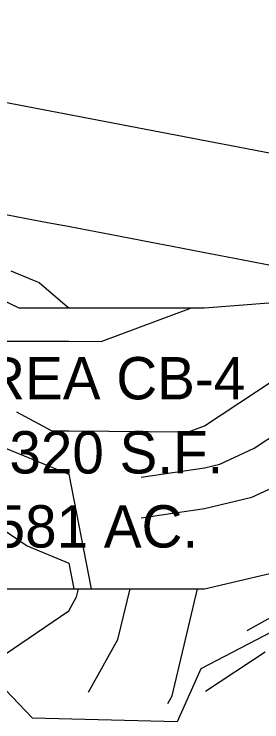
# Model space of a CAD drawing. Extents: x 2238 to 5457, y 2895 to 3316.
# Drawn here: x 3027 to 3085.6, y 3033.6 to 3200.8 of the extents above; entities that cross this region are included whole.
import ezdxf

# ---------------------------------------------------------------- set-up
doc = ezdxf.new("R2010")
doc.units = 0
for name, color, linetype in [('Default', 7, 'Continuous'), ('DESIGN - SCRATCH - User 2', 7, 'Continuous'), ('SURVEY - CENTERLINE - Preliminary', 7, 'Continuous'), ('SURVEY - DRAINAGE - Area Shapes', 7, 'Continuous')]:
    doc.layers.add(name, color=color, linetype=linetype)

msp = doc.modelspace()

# ---------------------------------------------------------------- linework, layer by layer
at = {"layer": 'DESIGN - SCRATCH - User 2'}
for points in [[(3025.06, 3153.5), (3029.97, 3152.56), (3034.88, 3151.62), (3039.79, 3150.68), (3044.7, 3149.74), (3049.61, 3148.8), (3054.53, 3147.86), (3059.44, 3146.92), (3064.35, 3145.98), (3069.26, 3145.04), (3074.17, 3144.1), (3079.08, 3143.16), (3083.99, 3142.22), (3088.9, 3141.28)], [(3025.06, 3153.5), (3029.97, 3152.56), (3034.88, 3151.62), (3039.79, 3150.68), (3044.7, 3149.74), (3049.61, 3148.8), (3054.53, 3147.86), (3059.44, 3146.92), (3064.35, 3145.98), (3069.26, 3145.04), (3074.17, 3144.1), (3079.08, 3143.16), (3083.99, 3142.22), (3088.9, 3141.28)], [(3025.06, 3153.5), (3029.97, 3152.56), (3034.88, 3151.62), (3039.79, 3150.68), (3044.7, 3149.74), (3049.61, 3148.8), (3054.53, 3147.86), (3059.44, 3146.92), (3064.35, 3145.98), (3069.26, 3145.04), (3074.17, 3144.1), (3079.08, 3143.16), (3083.99, 3142.22), (3088.9, 3141.28)], [(3025.06, 3153.5), (3029.97, 3152.56), (3034.88, 3151.62), (3039.79, 3150.68), (3044.7, 3149.74), (3049.61, 3148.8), (3054.53, 3147.86), (3059.44, 3146.92), (3064.35, 3145.98), (3069.26, 3145.04), (3074.17, 3144.1), (3079.08, 3143.16), (3083.99, 3142.22), (3088.9, 3141.28)], [(3025.06, 3153.5), (3029.97, 3152.56), (3034.88, 3151.62), (3039.79, 3150.68), (3044.7, 3149.74), (3049.61, 3148.8), (3054.53, 3147.86), (3059.44, 3146.92), (3064.35, 3145.98), (3069.26, 3145.04), (3074.17, 3144.1), (3079.08, 3143.16), (3083.99, 3142.22), (3088.9, 3141.28)], [(3025.06, 3153.5), (3029.97, 3152.56), (3034.88, 3151.62), (3039.79, 3150.68), (3044.7, 3149.74), (3049.61, 3148.8), (3054.53, 3147.86), (3059.44, 3146.92), (3064.35, 3145.98), (3069.26, 3145.04), (3074.17, 3144.1), (3079.08, 3143.16), (3083.99, 3142.22), (3088.9, 3141.28)], [(3025.06, 3153.5), (3029.97, 3152.56), (3034.88, 3151.62), (3039.79, 3150.68), (3044.7, 3149.74), (3049.61, 3148.8), (3054.53, 3147.86), (3059.44, 3146.92), (3064.35, 3145.98), (3069.26, 3145.04), (3074.17, 3144.1), (3079.08, 3143.16), (3083.99, 3142.22), (3088.9, 3141.28)], [(3025.06, 3153.5), (3029.97, 3152.56), (3034.88, 3151.62), (3039.79, 3150.68), (3044.7, 3149.74), (3049.61, 3148.8), (3054.53, 3147.86), (3059.44, 3146.92), (3064.35, 3145.98), (3069.26, 3145.04), (3074.17, 3144.1), (3079.08, 3143.16), (3083.99, 3142.22), (3088.9, 3141.28)], [(3025.06, 3153.5), (3029.97, 3152.56), (3034.88, 3151.62), (3039.79, 3150.68), (3044.7, 3149.74), (3049.61, 3148.8), (3054.53, 3147.86), (3059.44, 3146.92), (3064.35, 3145.98), (3069.26, 3145.04), (3074.17, 3144.1), (3079.08, 3143.16), (3083.99, 3142.22), (3088.9, 3141.28)], [(3025.06, 3153.5), (3029.97, 3152.56), (3034.88, 3151.62), (3039.79, 3150.68), (3044.7, 3149.74), (3049.61, 3148.8), (3054.53, 3147.86), (3059.44, 3146.92), (3064.35, 3145.98), (3069.26, 3145.04), (3074.17, 3144.1), (3079.08, 3143.16), (3083.99, 3142.22), (3088.9, 3141.28)], [(3025.06, 3153.5), (3029.97, 3152.56), (3034.88, 3151.62), (3039.79, 3150.68), (3044.7, 3149.74), (3049.61, 3148.8), (3054.53, 3147.86), (3059.44, 3146.92), (3064.35, 3145.98), (3069.26, 3145.04), (3074.17, 3144.1), (3079.08, 3143.16), (3083.99, 3142.22), (3088.9, 3141.28)], [(3025.06, 3153.5), (3029.97, 3152.56), (3034.88, 3151.62), (3039.79, 3150.68), (3044.7, 3149.74), (3049.61, 3148.8), (3054.53, 3147.86), (3059.44, 3146.92), (3064.35, 3145.98), (3069.26, 3145.04), (3074.17, 3144.1), (3079.08, 3143.16), (3083.99, 3142.22), (3088.9, 3141.28)], [(3025.06, 3153.5), (3029.97, 3152.56), (3034.88, 3151.62), (3039.79, 3150.68), (3044.7, 3149.74), (3049.61, 3148.8), (3054.53, 3147.86), (3059.44, 3146.92), (3064.35, 3145.98), (3069.26, 3145.04), (3074.17, 3144.1), (3079.08, 3143.16), (3083.99, 3142.22), (3088.9, 3141.28)], [(3025.06, 3153.5), (3029.97, 3152.56), (3034.88, 3151.62), (3039.79, 3150.68), (3044.7, 3149.74), (3049.61, 3148.8), (3054.53, 3147.86), (3059.44, 3146.92), (3064.35, 3145.98), (3069.26, 3145.04), (3074.17, 3144.1), (3079.08, 3143.16), (3083.99, 3142.22), (3088.9, 3141.28)], [(3025.06, 3153.5), (3029.97, 3152.56), (3034.88, 3151.62), (3039.79, 3150.68), (3044.7, 3149.74), (3049.61, 3148.8), (3054.53, 3147.86), (3059.44, 3146.92), (3064.35, 3145.98), (3069.26, 3145.04), (3074.17, 3144.1), (3079.08, 3143.16), (3083.99, 3142.22), (3088.9, 3141.28)], [(3025.06, 3153.5), (3029.97, 3152.56), (3034.88, 3151.62), (3039.79, 3150.68), (3044.7, 3149.74), (3049.61, 3148.8), (3054.53, 3147.86), (3059.44, 3146.92), (3064.35, 3145.98), (3069.26, 3145.04), (3074.17, 3144.1), (3079.08, 3143.16), (3083.99, 3142.22), (3088.9, 3141.28)], [(3025.06, 3153.5), (3029.97, 3152.56), (3034.88, 3151.62), (3039.79, 3150.68), (3044.7, 3149.74), (3049.61, 3148.8), (3054.53, 3147.86), (3059.44, 3146.92), (3064.35, 3145.98), (3069.26, 3145.04), (3074.17, 3144.1), (3079.08, 3143.16), (3083.99, 3142.22), (3088.9, 3141.28)], [(3025.06, 3153.5), (3029.97, 3152.56), (3034.88, 3151.62), (3039.79, 3150.68), (3044.7, 3149.74), (3049.61, 3148.8), (3054.53, 3147.86), (3059.44, 3146.92), (3064.35, 3145.98), (3069.26, 3145.04), (3074.17, 3144.1), (3079.08, 3143.16), (3083.99, 3142.22), (3088.9, 3141.28)], [(3025.06, 3153.5), (3029.97, 3152.56), (3034.88, 3151.62), (3039.79, 3150.68), (3044.7, 3149.74), (3049.61, 3148.8), (3054.53, 3147.86), (3059.44, 3146.92), (3064.35, 3145.98), (3069.26, 3145.04), (3074.17, 3144.1), (3079.08, 3143.16), (3083.99, 3142.22), (3088.9, 3141.28)], [(3025.06, 3153.5), (3029.97, 3152.56), (3034.88, 3151.62), (3039.79, 3150.68), (3044.7, 3149.74), (3049.61, 3148.8), (3054.53, 3147.86), (3059.44, 3146.92), (3064.35, 3145.98), (3069.26, 3145.04), (3074.17, 3144.1), (3079.08, 3143.16), (3083.99, 3142.22), (3088.9, 3141.28)], [(3025.06, 3153.5), (3029.97, 3152.56), (3034.88, 3151.62), (3039.79, 3150.68), (3044.7, 3149.74), (3049.61, 3148.8), (3054.53, 3147.86), (3059.44, 3146.92), (3064.35, 3145.98), (3069.26, 3145.04), (3074.17, 3144.1), (3079.08, 3143.16), (3083.99, 3142.22), (3088.9, 3141.28)], [(3025.06, 3153.5), (3029.97, 3152.56), (3034.88, 3151.62), (3039.79, 3150.68), (3044.7, 3149.74), (3049.61, 3148.8), (3054.53, 3147.86), (3059.44, 3146.92), (3064.35, 3145.98), (3069.26, 3145.04), (3074.17, 3144.1), (3079.08, 3143.16), (3083.99, 3142.22), (3088.9, 3141.28)], [(3025.06, 3153.5), (3029.97, 3152.56), (3034.88, 3151.62), (3039.79, 3150.68), (3044.7, 3149.74), (3049.61, 3148.8), (3054.53, 3147.86), (3059.44, 3146.92), (3064.35, 3145.98), (3069.26, 3145.04), (3074.17, 3144.1), (3079.08, 3143.16), (3083.99, 3142.22), (3088.9, 3141.28)], [(3025.06, 3153.5), (3029.97, 3152.56), (3034.88, 3151.62), (3039.79, 3150.68), (3044.7, 3149.74), (3049.61, 3148.8), (3054.53, 3147.86), (3059.44, 3146.92), (3064.35, 3145.98), (3069.26, 3145.04), (3074.17, 3144.1), (3079.08, 3143.16), (3083.99, 3142.22), (3088.9, 3141.28)], [(3025.06, 3153.5), (3029.97, 3152.56), (3034.88, 3151.62), (3039.79, 3150.68), (3044.7, 3149.74), (3049.61, 3148.8), (3054.53, 3147.86), (3059.44, 3146.92), (3064.35, 3145.98), (3069.26, 3145.04), (3074.17, 3144.1), (3079.08, 3143.16), (3083.99, 3142.22), (3088.9, 3141.28)], [(3025.06, 3153.5), (3029.97, 3152.56), (3034.88, 3151.62), (3039.79, 3150.68), (3044.7, 3149.74), (3049.61, 3148.8), (3054.53, 3147.86), (3059.44, 3146.92), (3064.35, 3145.98), (3069.26, 3145.04), (3074.17, 3144.1), (3079.08, 3143.16), (3083.99, 3142.22), (3088.9, 3141.28)], [(3026.25, 3140.13), (3031.4, 3138.01), (3032.92, 3137.38), (3039.68, 3131.7), (3039.93, 3131.49), (3039.94, 3131.48), (3039.97, 3131.46), (3040.02, 3131.44), (3072.01, 3131.44), (3087.24, 3132.62)], [(3023.57, 3123.59), (3039.93, 3123.54), (3047.62, 3123.49), (3068.96, 3131.44), (3072.01, 3131.44), (3087.24, 3132.62)], [(3024.02, 3133.42), (3028.13, 3131.44), (3039.93, 3131.41), (3039.96, 3131.41), (3040.05, 3131.44), (3072.01, 3131.44), (3087.24, 3132.62)], [(3027.59, 3106.83), (3035.94, 3102.38), (3039.93, 3102.37), (3068.23, 3102.16), (3072.01, 3103.57), (3088.45, 3114.43)], [(3057.07, 3091.41), (3072.01, 3093.67), (3075.62, 3094.52), (3083.74, 3098.26), (3096.16, 3106.45)], [(3025.03, 3098.26), (3039.93, 3092.11), (3045.24, 3065.07), (3072.01, 3065.07), (3098.14, 3071.22)], [(3057.07, 3081.8), (3072.01, 3084.06), (3083.18, 3086.69), (3104.08, 3096.31)], [(3015.09, 3085.38), (3030.15, 3075.19), (3039.93, 3071.15), (3041.12, 3065.07), (3072.01, 3065.07), (3098.14, 3071.22)], [(3007.85, 3065.07), (3039.93, 3065.07), (3072.01, 3065.07), (3098.14, 3071.22)], [(3007.85, 3065.07), (3039.93, 3065.07), (3072.01, 3065.07), (3098.14, 3071.22)], [(3007.85, 3065.07), (3039.93, 3065.07), (3072.01, 3065.07), (3098.14, 3071.22)], [(3007.85, 3065.07), (3039.93, 3065.07), (3072.01, 3065.07), (3098.14, 3071.22)], [(3007.85, 3065.07), (3039.93, 3065.07), (3072.01, 3065.07), (3098.14, 3071.22)], [(3007.85, 3065.07), (3039.93, 3065.07), (3072.01, 3065.07), (3098.14, 3071.22)], [(3024.91, 3049.63), (3039.93, 3059.85), (3041.79, 3063.15), (3042.25, 3065.07), (3072.01, 3065.07), (3098.14, 3071.22)], [(3026.48, 3065.07), (3039.93, 3065.07), (3072.01, 3065.07), (3098.14, 3071.22)], [(3044.57, 3040.69), (3051.54, 3053.06), (3054.41, 3065.07), (3072.01, 3065.07), (3098.14, 3071.22)], [(3063.33, 3038.01), (3064.34, 3039.81), (3070.39, 3065.07), (3072.01, 3065.07), (3098.14, 3071.22)], [(3082.09, 3055.21), (3099.84, 3065.07)], [(3072.26, 3040.91), (3086.38, 3050.2)]]:
    msp.add_lwpolyline(points, dxfattribs=at)
at = {"layer": 'SURVEY - CENTERLINE - Preliminary'}
msp.add_lwpolyline([(3025.06, 3153.5), (3029.97, 3152.56), (3034.88, 3151.62), (3039.79, 3150.68), (3044.7, 3149.74), (3049.61, 3148.8), (3054.53, 3147.86), (3059.44, 3146.92), (3064.35, 3145.98), (3069.26, 3145.04), (3074.17, 3144.1), (3079.08, 3143.16), (3083.99, 3142.22), (3088.9, 3141.28)], dxfattribs=at)
at = {"layer": 'SURVEY - DRAINAGE - Area Shapes'}
for points in [[(2916.24, 3200.79), (3158.5, 3154.43), (3193.63, 3123.59)], [(3193.63, 3123.59), (3174.77, 3103.59), (3154.23, 3089.74), (3133.68, 3076.53), (3087.9, 3054.88), (3071.15, 3046.16), (3065.56, 3033.65), (3031.39, 3034.54), (3010.4, 3056.44), (2981.93, 3079.71), (2979.58, 3101.81)]]:
    msp.add_lwpolyline(points, dxfattribs=at)

# ---------------------------------------------------------------- texts
at = {"layer": 'Default'}
for s, p in [('AREA CB-4', (3011.04, 3109.81)), ('25320 S.F.', (3011.04, 3092.31)), ('0.581 AC.', (3011.04, 3074.81))]:
    msp.add_text(s, height=10, dxfattribs=at).set_placement(p)

doc.saveas('drawing.dxf')
